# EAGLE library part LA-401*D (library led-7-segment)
Single Digit LED Numeric Display (anode common) Source: ROHM .. la-1401dn.pdf
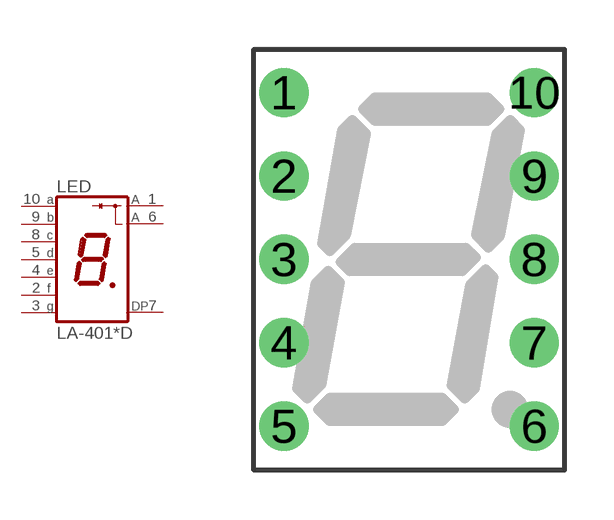
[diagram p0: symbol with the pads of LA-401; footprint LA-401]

Designator prefix LED

## LA-401AD (OC_FARNELL: unknown; OC_NEWARK: unknown), LA-401BD (OC_FARNELL: unknown; OC_NEWARK: unknown), LA-401ED (OC_FARNELL: unknown; OC_NEWARK: unknown), LA-401MD (OC_FARNELL: unknown; OC_NEWARK: unknown), LA-401VD (OC_FARNELL: unknown; OC_NEWARK: unknown), LA-401XD (OC_FARNELL: unknown; OC_NEWARK: unknown)  [LA-401]
1  A  pas
2  F  pas
3  G  pas
4  E  pas
5  D  pas
6  A  pas
7  DP  pas
8  C  pas
9  B  pas
10  A  pas

## Footprint LA-401 (pad centres in mm)
Single Digit LED Numeric Display 10.16 mm Source: ROHM .. la-401dn.pdf
drill 0.9 pad 1.5 round: 1 -3.81,5.08; 2 -3.81,2.54; 3 -3.81,0; 4 -3.81,-2.54; 5 -3.81,-5.08; 6 3.81,-5.08; 7 3.81,-2.54; 8 3.81,0; 9 3.81,2.54; 10 3.81,5.08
